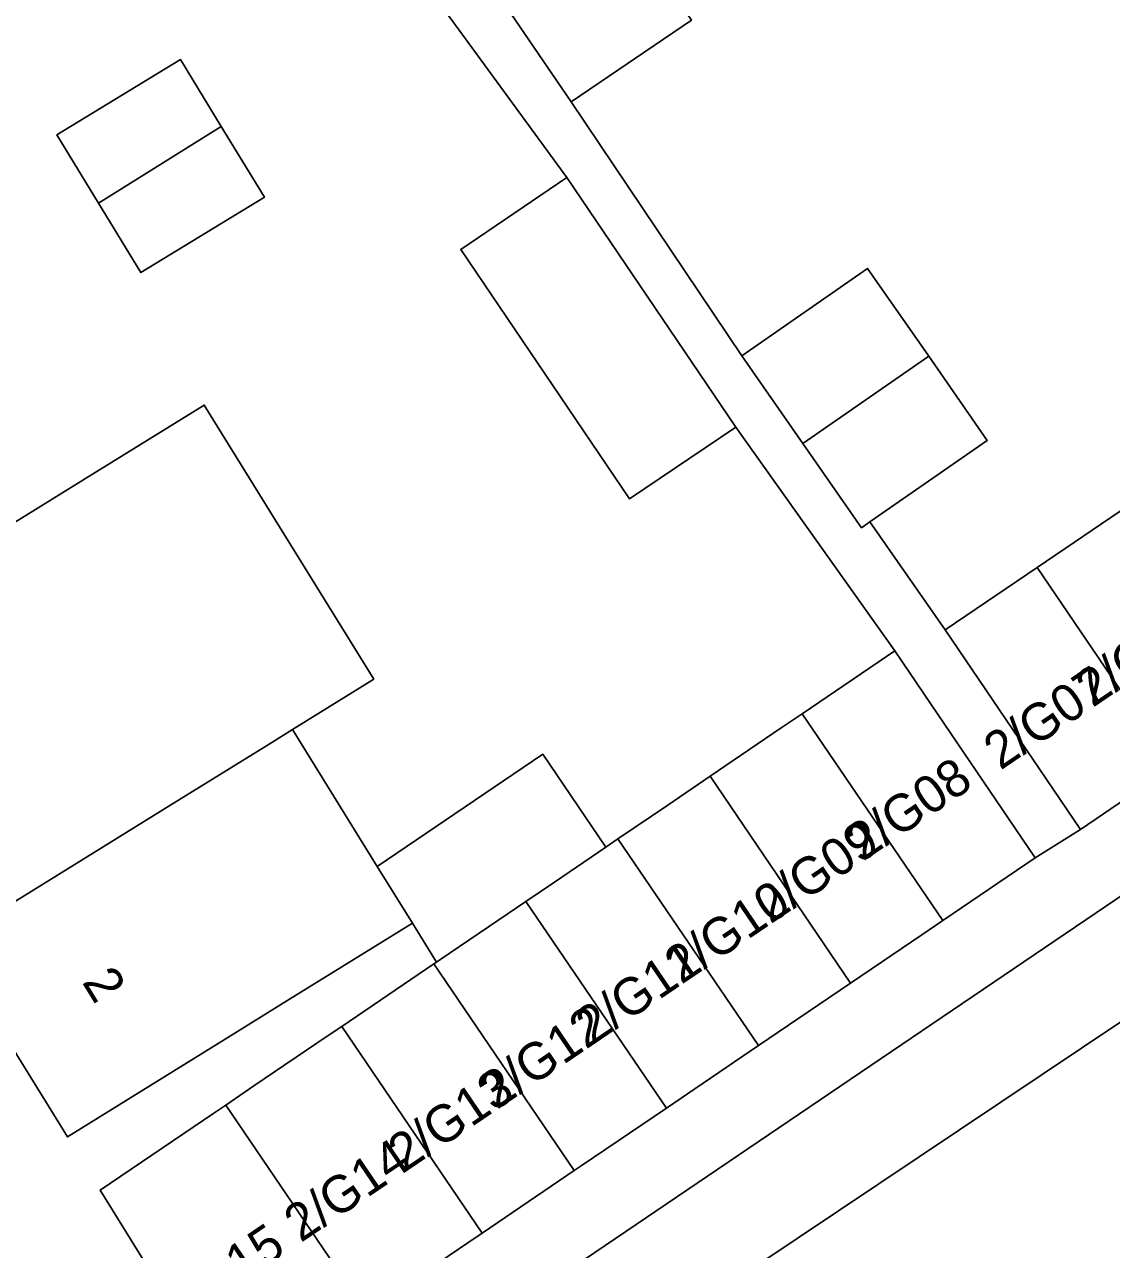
# Model space of a CAD drawing. Extents: x 159664 to 160323, y 385312 to 386115.
# Drawn here: x 160206.93 to 160236.22, y 385719.4 to 385752.41 of the extents above; entities that cross this region are included whole.
import ezdxf

# ---------------------------------------------------------------- set-up
doc = ezdxf.new("R2010")
doc.units = 0
for name, color, linetype in [('IMGEO_Erf', 7, 'Continuous'), ('IMGEO_Pand', 7, 'Continuous'), ('IMGEO_Pand_nummerreeks', 7, 'Continuous'), ('IMGEO_Rijbaan_lokaal_open', 7, 'Continuous'), ('IMGEO_Voetpad_open', 7, 'Continuous')]:
    doc.layers.add(name, color=color, linetype=linetype)

msp = doc.modelspace()

# ---------------------------------------------------------------- linework, layer by layer
at = {"layer": 'IMGEO_Erf'}
for points in [[(160206.2, 385738.709), (160208.943, 385740.407), (160211.768, 385742.156), (160216.34, 385734.769), (160214.15, 385733.411), (160216.435, 385729.718), (160220.893, 385732.747), (160222.595, 385730.243), (160222.921, 385730.464), (160224.265, 385731.376), (160225.403, 385732.149), (160227.324, 385733.452), (160227.885, 385733.833), (160230.383, 385735.528), (160226.094, 385741.562), (160223.235, 385739.626), (160218.682, 385746.349), (160221.541, 385748.285), (160214.448, 385758.009), (160211.055, 385755.891), (160207.871, 385760.991), (160210.776, 385762.792), (160207.315, 385767.854), (160204.933, 385766.207)], [(160224.899, 385752.532), (160221.66, 385750.323), (160226.261, 385743.483), (160229.648, 385745.839), (160231.297, 385743.47), (160232.872, 385741.204), (160229.711, 385739.005), (160231.739, 385736.1), (160234.221, 385737.778), (160236.71, 385739.462), (160239.2, 385741.146), (160241.689, 385742.829), (160244.179, 385744.513), (160245.115, 385745.146), (160241.431, 385750), (160240.869, 385750.74), (160236.522, 385756.467)], [(160186.266, 385750), (160208.863, 385713.863), (160209.011, 385713.648), (160209.177, 385713.448), (160209.36, 385713.263), (160209.56, 385713.095), (160209.773, 385712.946), (160209.999, 385712.817), (160210.235, 385712.708), (160210.481, 385712.62), (160210.733, 385712.555), (160210.99, 385712.513), (160211.25, 385712.494), (160211.51, 385712.498), (160211.769, 385712.526), (160212.024, 385712.576), (160212.274, 385712.649), (160212.517, 385712.744), (160212.75, 385712.86), (160212.967, 385712.994), (160213.887, 385713.618), (160217.895, 385716.335), (160253.974, 385740.781), (160258.951, 385744.343)], [(160237.871, 385732.407), (160235.385, 385730.718), (160234.166, 385729.95), (160231.674, 385728.259), (160231.108, 385727.876), (160229.191, 385726.575), (160228.049, 385725.8), (160226.708, 385724.891), (160224.989, 385723.725), (160224.225, 385723.207), (160221.929, 385721.649), (160221.742, 385721.522), (160219.26, 385719.839), (160218.87, 385719.574), (160216.131, 385717.716)], [(160212.516, 385715.264), (160208.969, 385720.996), (160212.028, 385723.072), (160212.35, 385723.29), (160213.107, 385723.804), (160215.087, 385725.148), (160215.474, 385725.41), (160217.956, 385727.094), (160218.029, 385727.144), (160217.382, 385728.189), (160214.072, 385726.14), (160212.332, 385725.063), (160208.08, 385722.432), (160204.849, 385727.653)]]:
    msp.add_lwpolyline(points, dxfattribs=at)
msp.add_lwpolyline([(160211.126, 385751.467), (160212.225, 385749.666), (160213.392, 385747.756), (160210.061, 385745.723), (160208.916, 385747.6), (160207.796, 385749.434)], close=True, dxfattribs=at)
at = {"layer": 'IMGEO_Pand'}
for points in [[(160223.14, 385755.109), (160219.902, 385752.901), (160221.66, 385750.323), (160224.899, 385752.532)], [(160208.916, 385747.6), (160212.225, 385749.666), (160211.126, 385751.467), (160207.796, 385749.434)], [(160212.225, 385749.666), (160208.916, 385747.6), (160210.061, 385745.723), (160213.392, 385747.756)], [(160218.682, 385746.349), (160223.235, 385739.626), (160226.094, 385741.562), (160221.541, 385748.285)], [(160226.261, 385743.483), (160227.905, 385741.119), (160231.297, 385743.47), (160229.648, 385745.839)], [(160231.297, 385743.47), (160227.905, 385741.119), (160229.485, 385738.848), (160229.711, 385739.005), (160232.872, 385741.204)], [(160211.768, 385742.156), (160208.943, 385740.407), (160206.2, 385738.709), (160200.316, 385735.036), (160201.616, 385732.876), (160204.849, 385727.653), (160210.84, 385731.362), (160213.516, 385733.018), (160214.15, 385733.411), (160216.34, 385734.769)], [(160237.871, 385732.407), (160240.356, 385734.096), (160236.71, 385739.462), (160234.221, 385737.778)], [(160234.221, 385737.778), (160231.739, 385736.1), (160235.385, 385730.718), (160237.871, 385732.407)], [(160234.166, 385729.95), (160231.359, 385734.088), (160230.383, 385735.528), (160227.885, 385733.833), (160231.674, 385728.259)], [(160231.108, 385727.876), (160231.674, 385728.259), (160227.885, 385733.833), (160227.324, 385733.452), (160225.403, 385732.149), (160229.191, 385726.575)], [(160217.382, 385728.189), (160216.435, 385729.718), (160214.15, 385733.411), (160213.516, 385733.018), (160210.84, 385731.362), (160204.849, 385727.653), (160208.08, 385722.432), (160212.332, 385725.063), (160214.072, 385726.14)], [(160222.595, 385730.243), (160220.893, 385732.747), (160216.435, 385729.718), (160217.382, 385728.189), (160218.029, 385727.144), (160218.146, 385727.224), (160220.438, 385728.779), (160221.206, 385729.3)], [(160222.921, 385730.464), (160226.708, 385724.891), (160228.049, 385725.8), (160229.191, 385726.575), (160225.403, 385732.149), (160224.265, 385731.376)], [(160222.921, 385730.464), (160222.595, 385730.243), (160221.206, 385729.3), (160220.438, 385728.779), (160224.225, 385723.207), (160224.989, 385723.725), (160226.708, 385724.891)], [(160220.438, 385728.779), (160218.146, 385727.224), (160218.029, 385727.144), (160217.956, 385727.094), (160221.742, 385721.522), (160221.929, 385721.649), (160224.225, 385723.207)], [(160221.742, 385721.522), (160217.956, 385727.094), (160215.474, 385725.41), (160219.26, 385719.839)], [(160218.87, 385719.574), (160219.26, 385719.839), (160215.474, 385725.41), (160215.087, 385725.148), (160213.107, 385723.804), (160212.35, 385723.29), (160216.131, 385717.716)], [(160216.131, 385717.716), (160212.35, 385723.29), (160212.028, 385723.072), (160208.969, 385720.996), (160212.516, 385715.264), (160215.81, 385717.499)]]:
    msp.add_lwpolyline(points, close=True, dxfattribs=at)
at = {"layer": 'IMGEO_Rijbaan_lokaal_open'}
msp.add_lwpolyline([(160262.889, 385743.364), (160255.558, 385738.437), (160239.787, 385727.747), (160216.828, 385712.381), (160215.287, 385711.356), (160214.735, 385710.989), (160214.143, 385710.596), (160213.944, 385710.46)], dxfattribs=at)
at = {"layer": 'IMGEO_Voetpad_open'}
msp.add_lwpolyline([(160203.94, 385772.736), (160207.315, 385767.854), (160210.776, 385762.792), (160211.271, 385763.099), (160214.448, 385758.009), (160221.541, 385748.285), (160226.094, 385741.562), (160230.383, 385735.528), (160231.359, 385734.088), (160234.166, 385729.95), (160235.385, 385730.718), (160231.739, 385736.1), (160229.711, 385739.005), (160229.485, 385738.848), (160227.905, 385741.119), (160226.261, 385743.483), (160221.66, 385750.323), (160219.902, 385752.901), (160218.143, 385755.478), (160213.342, 385762.357), (160211.603, 385764.843), (160209.976, 385767.17), (160204.116, 385775.667)], dxfattribs=at)
msp.add_lwpolyline([(160239.787, 385727.747), (160255.558, 385738.437), (160253.974, 385740.781), (160217.895, 385716.335), (160213.887, 385713.618), (160215.287, 385711.356), (160216.828, 385712.381)], close=True, dxfattribs=at)

# ---------------------------------------------------------------- texts
at = {"layer": 'IMGEO_Pand_nummerreeks'}
for s, rotation, p in [('2/G06', 34.1954, (160235.713, 385733.988)), ('2/G07', 34.1954, (160233.228, 385732.299)), ('2/G08', 34.1505, (160229.523, 385729.845)), ('2/G09', 34.1505, (160227.03, 385728.154)), ('2/G10', 34.1505, (160224.628, 385726.525)), ('2/G11', 34.1483, (160222.234, 385724.901)), ('2', 301.7531, (160208.461, 385726.605)), ('2/G12', 34.1483, (160219.655, 385723.151)), ('2/G13', 34.1505, (160217.177, 385721.471)), ('2/G14', 34.1505, (160214.371, 385719.568)), ('2/G15', 34.1505, (160210.999, 385717.28))]:
    msp.add_text(s, height=1, rotation=rotation, dxfattribs=at).set_placement(p)

doc.saveas('drawing.dxf')
